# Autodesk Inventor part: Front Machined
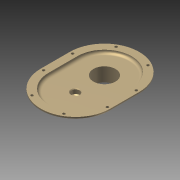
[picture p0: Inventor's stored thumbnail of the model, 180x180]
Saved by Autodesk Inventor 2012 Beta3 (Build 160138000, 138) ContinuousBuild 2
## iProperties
Created: 2010-12
Part Number: Front Machined
Material: Default
Document SubType Name: Modeling
Designer: Beta-8540w
Density: 1 g/cm^3
Author: Beta-8540w
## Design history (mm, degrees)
node "c8-09" dims "d0" = 10
hole "Hole1" diameter "d3" = 14; stored, may be unused: countersink angle "d7" = 90 deg, drill point angle "d9" = 118 deg; dims "d1" = 10, "d2" = 10, "d4" = 6, "d5" = 4, "d6" = 2, "d8" = 8
workplane "Work Plane1"
split "Split1"
workplane "Work Plane2"
split "Split2"
hole "Hole2" diameter "d14" = 3.242; stored, may be unused: countersink angle "d18" = 90 deg, drill point angle "d20" = 118 deg; dims "d12" = 10, "d13" = 10, "d15" = 8, "d16" = 4, "d17" = 2, "d19" = 10
pattern_circular "Circular Pattern1" dims angle "d22" = 360 deg
hole "Hole3" diameter "d26" = 38; stored, may be unused: countersink angle "d30" = 90 deg, drill point angle "d32" = 118 deg; dims "d27" = 8, "d28" = 4, "d29" = 2, "d31" = 10, "d45" = 10, "d46" = 10
sketch "Sketch2"
  geometry: L1 (-59.93, 0)-(-59.93, 50) reference; L2 (59.93, 50)-(59.93, 0) reference; L3 (-55, 50)-(-55, 0); L4 (55, 0)-(55, 50); A1 r 59.93 centre (0, 0) between (-59.93, 0) and (59.93, 0) reference; A2 r 59.93 centre (0, 50) between (59.93, 50) and (-59.93, 50) reference; A3 r 55 centre (0, 0) between (-55, 0) and (55, 0); A4 r 55 centre (0, 50) between (55, 50) and (-55, 50); 8 further points
  constraints: 8 point on circle, 4 coincident, 4 end point, 2 centre point, 2 horizontal alignment, 2 vertical alignment, 3 other
  dimensions: "d33" = 55 radius of A4; "d34" = 55 distance of point (27.5, 97.631) point (-27.5, 97.631)
hole "Hole4" sketch "Sketch2" at (-55, 0), (55, 0), (55, 50), (-55, 50), (-27.5, 97.631), (27.5, 97.631), (27.5, -47.631), (-27.5, -47.631) diameter "d35" = 4.5; stored, may be unused: countersink angle "d39" = 90 deg, drill point angle "d41" = 118 deg; dims "d36" = 8, "d37" = 4, "d38" = 90, "d40" = 10
chamfer "Chamfer1" distance "d42" = 1; stored, may be unused: second distance "d43" = 2, angle "d44" = 45 deg
feature "Solid1::Front cast.ipt" dims "d0" = 10
tag "TaggingFeature1"
body "Solid1"
other parameters: "d10" = -3, "d11" = -29
